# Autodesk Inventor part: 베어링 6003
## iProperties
IsCustomPart: 1
Created: 2009-02
Part Number: 베어링 6003
Material: 강, 연강
Description: 깊은 그루브 볼 베어링
Document SubType Name: Modeling
Standard: KS B 2023
Designer: 한국산업디자인학원
Standards Organization: KS
Language: ko-KR
Size Designation: 6003 - 17 x 35 x 10
Categories: <MemberInstance><Categories><Category DisplayName="샤프트 부품" InternalName="7f7aeb1f-a693-4053-b835-cee3144e0d98" Mnemonic="SHFT"><Category DisplayName="베어링" Inter
Density: 1 g/cm^3
Author: 한국산업디자인학원
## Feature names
1. IDS_ARRAYBALL[SIMPL:T] [Circular Pattern]
